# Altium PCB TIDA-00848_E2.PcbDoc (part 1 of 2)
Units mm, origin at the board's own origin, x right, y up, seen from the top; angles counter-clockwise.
Board outline 40 x 87.63 mm, 2 copper layers (Top Layer, Bottom Layer), stack 0.98 mm thick; 101 components, 66 nets, 314 pads, 292 vias.
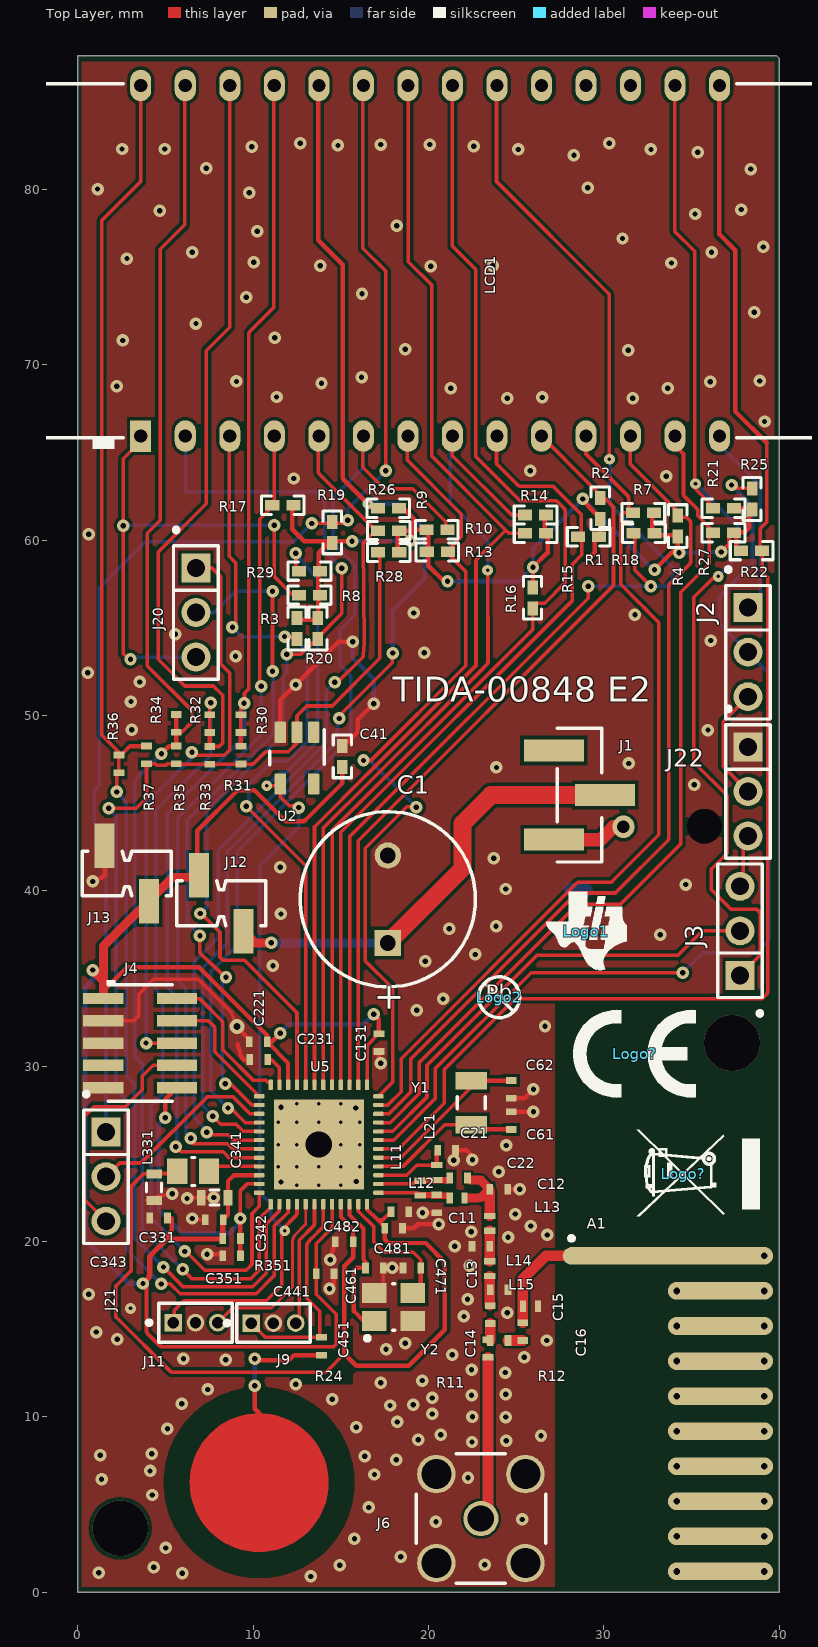
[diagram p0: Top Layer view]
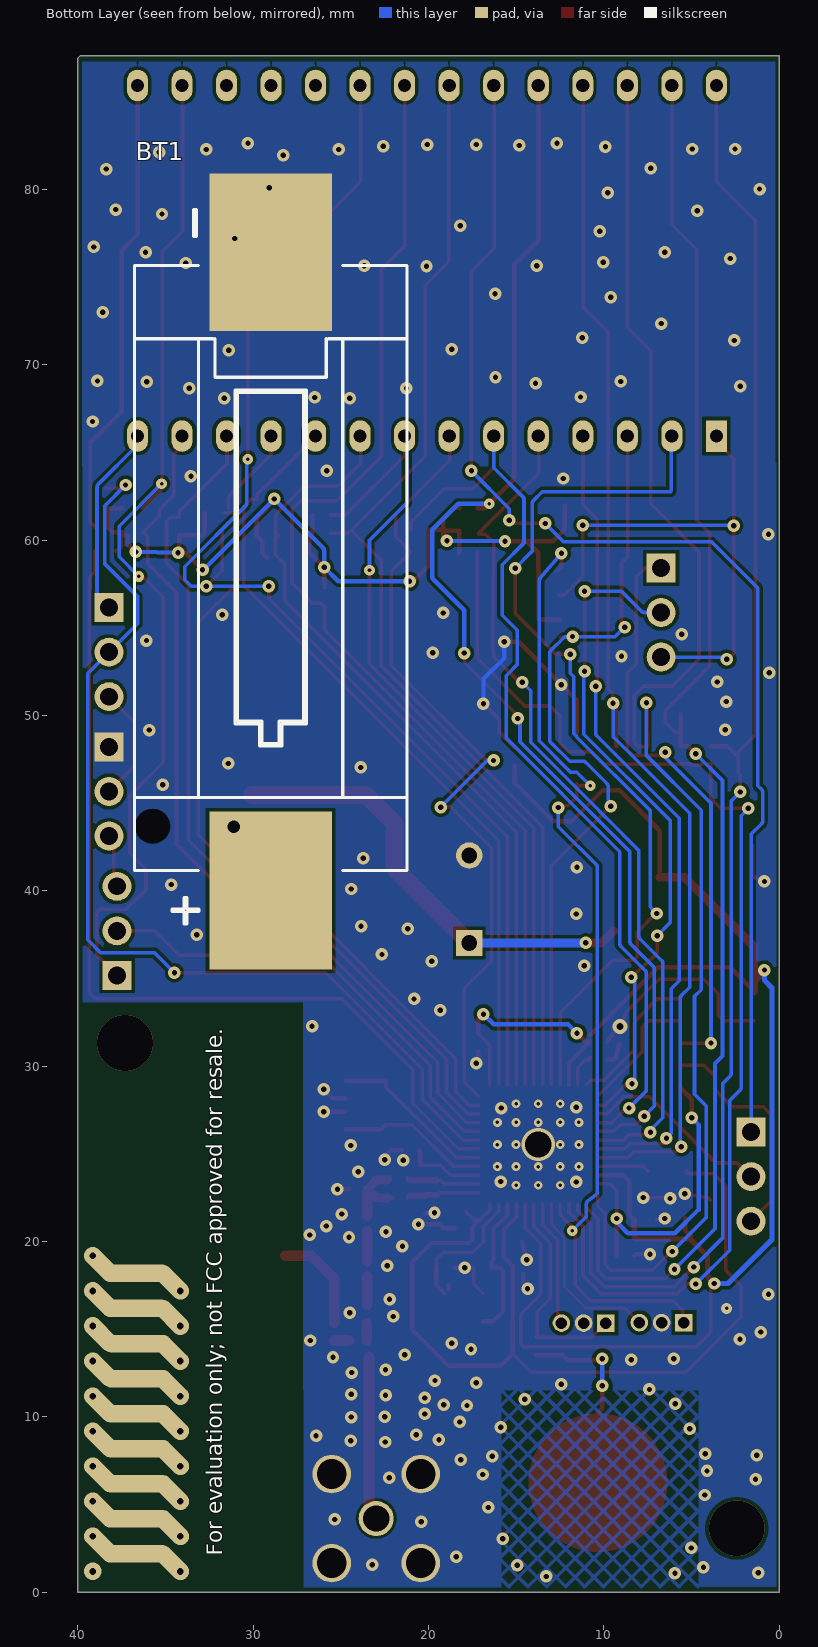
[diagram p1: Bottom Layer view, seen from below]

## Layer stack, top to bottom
Top Solder: solder mask 0.0102, Solder Resist, Dk 3.5
Top Layer: signal copper 0.035
Dielectric1: core 0.91, FR-4, Dk 4.6
Bottom Layer: signal copper 0.035
Bottom Solder: solder mask 0.0102, Solder Resist, Dk 3.5

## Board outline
0,0 40,0 40,87.508 39.878,87.63 0,87.63

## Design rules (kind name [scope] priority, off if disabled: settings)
AssemblyTestPointUsage [All] p1: valid=2
Clearance Clearance_Keepouts [((IsTrack Or IsArc) And Not InPoly) And IsFree and IsKeepOut vs ((IsTrack Or IsArc) And Not InPoly) And IsFree and IsKeepOut] p1: gap=0 ignorepadtopadclearanceinfootprint=FALSE
Clearance Clearance_BoardEdge_MountingHoles [OnCopper and InComponentClass('Mounting Holes') vs IsKeepOut] p2: gap=1.016 ignorepadtopadclearanceinfootprint=FALSE except(0: Arc-Hole Track-Hole SMDPad-Hole THPad-Hole Via-Hole Fill-Hole Poly-Hole Region-Hole Text-Hole)
Clearance Clearance_BoardEdge_Poly [OnCopper and InPoly vs IsKeepOut] p3: gap=0.635 ignorepadtopadclearanceinfootprint=FALSE except(0: Arc-Hole Track-Hole SMDPad-Hole THPad-Hole Via-Hole Fill-Hole Poly-Hole Region-Hole Text-Hole)
Clearance Clearance_BoardEdge [OnCopper and Not InComponentClass('Logo') and not InComponentClass('FiducialMark') and not InRegion(1000,500,4000,800) and Not IsKeepout vs IsKeepOut] p4: gap=1.905 ignorepadtopadclearanceinfootprint=FALSE except(0: Arc-Hole Track-Hole SMDPad-Hole THPad-Hole Via-Hole Fill-Hole Poly-Hole Region-Hole Text-Hole)
Clearance Clearance_CAP [InNet('CAP_EL') vs InNet('GND')] p5: gap=1.5 ignorepadtopadclearanceinfootprint=FALSE except(0: Arc-Hole Track-Hole SMDPad-Hole THPad-Hole Via-Hole Fill-Hole Poly-Hole Region-Hole Text-Hole; 0.254: Arc-Track Arc-SMDPad Arc-THPad Arc-Via Track-Track Track-Via Track-Poly SMDPad-Via THPad-Via Via-Via Via-Fill Via-Poly)
Clearance Clearance_015 [InPolygon vs (InNet('NetC12_1') OR InNet('NetC13_1') OR InNet('NetC14_1') OR InNet('NetC15_2') OR InNet('NetC16_2') OR InNet('NetA1_1') OR InNet('NetJ6_1') )] p6: gap=0.15 ignorepadtopadclearanceinfootprint=FALSE except(0: Arc-Hole Track-Hole SMDPad-Hole THPad-Hole Via-Hole Fill-Hole Poly-Hole Region-Hole Text-Hole)
Clearance Clearance_Poly [InPolygon] p7: gap=0.2 ignorepadtopadclearanceinfootprint=FALSE except(0: Arc-Hole Track-Hole SMDPad-Hole THPad-Hole Via-Hole Fill-Hole Poly-Hole Region-Hole Text-Hole)
Clearance [All] p8: gap=0.2 ignorepadtopadclearanceinfootprint=FALSE except(0: Arc-Hole Track-Hole SMDPad-Hole THPad-Hole Via-Hole Fill-Hole Poly-Hole Region-Hole Text-Hole)
ComponentClearance [All] p1: gap=0.254 collisioncheckmode=3 verticalgap=0.254 showdistances=TRUE
DiffPairsRouting [All] p1: maxlimit=2.54 minlimit=0.254 mostfreqgap=0.254 toplayer_minwidth=0.381 toplayer_maxwidth=0.381 toplayer_prefwidth=0.381 bottomlayer_minwidth=0.381 bottomlayer_maxwidth=0.381 bottomlayer_prefwidth=0.381 maxuncoupledlength=25.4
FabricationTestPointUsage TestPointUsage [All] p1: valid=2 allowmultiple=FALSE
FabricationTestpoint Testpoint [All] p1: side=3 testpointundercomponent=TRUE minsize=1.016 maxsize=2.54 preferedsize=1.524 minholesize=0 maxholesize=1.016 preferedholesize=0.813 testpointgrid=0.025 allowsidetop=TRUE allowsidebottom=TRUE usegrid=TRUE gridtolerance=0
FanoutControl Fanout_LCC [IsLCC] p1: bgadir=Out bgaviamode=Centered fanoutstyle=Auto fanoutdirection=Alternating viagrid=0.025 // Fanout_LCC (Default Rule)
FanoutControl Fanout_BGA [IsBGA] p2: bgadir=Out bgaviamode=Centered fanoutstyle=Auto fanoutdirection=Alternating viagrid=0.025 // Fanout_BGA (Default Rule)
FanoutControl Fanout_Default [All] p4: bgadir=Out bgaviamode=Centered fanoutstyle=Auto fanoutdirection=Alternating viagrid=0.025 // Fanout_Default (Default Rule)
FanoutControl Fanout_Small [(CompPinCount < 5)] p5: bgadir=Out bgaviamode=Centered fanoutstyle=Auto fanoutdirection=OutThenIn viagrid=0.025 // Fanout_Small (Default Rule)
HoleSize [All] p1: absolutevalues=TRUE maxlimit=6 minlimit=0.2 maxpercent=80.000 minpercent=20.000
HoleSize FabricationTestpoint [All] p2 off: absolutevalues=TRUE maxlimit=2.54 minlimit=0.025 maxpercent=80.000 minpercent=20.000
HoleSize FabricationTestPointUsage [All] p3 off: absolutevalues=TRUE maxlimit=2.54 minlimit=0.025 maxpercent=80.000 minpercent=20.000
MinimumSolderMaskSliver [All] p1: minsoldermaskwidth=0.152
PlaneClearance [All] p1: clearance=0.2
PlaneConnect [All] p1: planeconnectstyle=Relief reliefexpansion=0.254 reliefentries=4 reliefconductorwidth=0.254 reliefairgap=0.254
PolygonConnect PolygonConnect_GND [HasPad('U5-49') OR HasPad('U4')] p1: connectstyle=NoConnect reliefconductorwidth=0.254 reliefentries=4 polygonreliefangle="90 Angle" airgapwidth=0.254
PolygonConnect [All] p2: connectstyle=Direct reliefconductorwidth=0.254 reliefentries=4 polygonreliefangle="90 Angle" airgapwidth=0.254
RoutingVias ThermalPadVias [IsVia and InAnyComponent] p1: holewidth=0.2 width=0.5 viastyle="Through Hole" minholewidth=0.2 minwidth=0.5 maxholewidth=0.39 maxwidth=0.6
RoutingVias [All] p2: holewidth=0.2 width=0.864 viastyle="Through Hole" minholewidth=0.2 minwidth=0.66 maxholewidth=0.4 maxwidth=1.651
SilkToSilkClearance [All] p1: silktosilkclearance=0.178
SilkToSolderMaskClearance [IsPad] p1: minsilkscreentomaskgap=0.152 clearancetoexposedcopper=TRUE
SolderMaskExpansion [All] p1: expansion=0.05 istentingtop=FALSE
SupplyNets "Schematic Supply Nets_5" [InNet('VCC_430')] p1: voltage=0.000
SupplyNets "Schematic Supply Nets_4" [InNet('VCC_IN')] p2: voltage=0.000
SupplyNets "Schematic Supply Nets_3" [InNet('VDDS')] p3: voltage=0.000
SupplyNets "Schematic Supply Nets_2" [InNet('VCC_EXTERN')] p4: voltage=0.000
SupplyNets "Schematic Supply Nets_1" [InNet('GND')] p5: voltage=0.000
SupplyNets "Schematic Supply Nets" [InNet('VDDR')] p6: voltage=0.000
Width [All] p1: maxlimit=2.54 minlimit=0.152 preferedwidth=0.254 checkconnectedcopper=TRUE
15 further rules are at their usual default settings.

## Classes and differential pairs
component class Header: J1 J2 J3 J4 J9 J11 J12 J13 J20 J21 J22
component class TIDA-00848_RF_E2: A1 C11 C12 C13 C14 C15 C16 C21 C22 C61 C62 C131 C221 C231 C331 C341 C342 C343 C351 C441 C451 C461 C471 C481 C482 J4 J6 J9 J11 L11 L12 L13 L14 L15 L21 L331 R11 R12 R24 R351 U5 Y1 Y2
component class TIDA-00848_LCD_E2: BT1 C1 C41 J1 J2 J3 J12 J13 J20 J21 J22 LCD1 R1 R2 R3 R4 R7 R8 R9 R10 R13 R14 R15 R16 R17 R18 R19 R20 R21 R22 R25 R26 R27 R28 R29 R30 R31 R32 R33 R34 R35 R36 R37 U2
component class Logo: Logo1
component class TIDA-00848__Hardware_E2: FID1 FID2 H9 H10 H11 Logo1 Logo2 Logo? ZZ2 ZZ3 ZZ4
component class FiducialMark: FID1 FID2
component class AssemblyNote: ZZ2 ZZ3 ZZ4

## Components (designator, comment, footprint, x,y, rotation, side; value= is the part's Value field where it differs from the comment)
A1 "ANTENNA_HELICAL" ANTENNA_HELICAL 28.155,19.177 r270 top locked net-tie
BT1 "1010" BAT_1010 29.008,58.228 r90 bottom locked
C1 "EEUFM1A122" CAPPR5-10X20 17.678,39.522 r90 top locked value=1200uF
C11 "Comment" 0402S 20.472,22.149 r90 top value=3.6pF
C12 "GRM1555C1H2R7CA01D" 0402S 24.003,22.987 r0 top value=2.7pF
C13 "GRM1555C1H6R2CA01D" 0402S 22.987,19.736 r180 top value=6.2pF
C14 "GRM1555C1H3R3CA01D" 0402S 24.028,17.247 r0 top value=3.3pF
C15 "GRM1555C1H101JA01D" 0402S 23.52,15.824 r270 top value=100pF
C16 "GRM1555C1H1R0CA01D" 0402S 25.375,14.859 r270 top value=1pF
C21 "GRM1555C1H101JA01D" 0402S 21.029,25.203 r180 top value=100pF
C22 "GRM1555C1H3R6CA01D" 0402S 21.717,23.622 r0 top value=3.6pF
C41 "CMP-0006607-2" 0402 15.088,47.676 r90 top value=0.1uF
C61 "Comment" 0402S 24.714,26.899 r90 top value=12pF
C62 "GRM1555C1H120JA01D" 0402S 24.714,28.677 r270 top value=12pF
C131 "Comment" 0402S 17.17,31.344 r270 top value=0.1uF
C221 "Comment" 0402S 10.287,31.394 r180 top value=0.1uF
C231 "Comment" 0402S 10.312,30.378 r180 top value=1uF
C331 "GRM188R60J226MEA0J" 0603S 4.343,23.089 r270 top value=22uF
C341 "GRM188R60J226MEA0J" 0603S 7.798,22.504 r180 top value=22uF
C342 "GRM155R61E104KA87D" 0402S 7.772,21.234 r180 top value=0.1uF
C343 "GRM155R61E104KA87D" 0402S 4.597,21.336 r180 top value=0.1uF
C351 "GRM155R70J104KA01D" 0402S 8.763,19.177 r180 top value=0.1uF
C441 "GRM155R70J104KA01D" 0402S 14.097,18.161 r0 top value=0.1uF
C451 "GRM155R70J104KA01D" 0402S 15.189,19.99 r180 top value=0.1uF
C461 "DNM" 0402S 16.916,18.491 r0 top value=12pF
C471 "DNM" 0402S 19.05,18.491 r180 top value=12pF
C481 "GRM155R70J104KA01D" 0402S 18.009,20.752 r0 top value=0.1uF
C482 "GRM155R70J104KA01D" 0402S 18.364,21.692 r0 top value=0.1uF
FID1 "Fiducial" Fiducial10-20 53.721,1.092 r0 top
FID2 "Fiducial" Fiducial10-20 57.963,1.092 r0 top
FID3 "Fiducial" Fiducial10-20 62.23,1.092 r0 top
H9 "SJ-5303 (CLEAR)" Bumpon_SJ5003Transparent 82.474,13.259 r0 top
H10 "SJ-5303 (CLEAR)" Bumpon_SJ5003Transparent 55.728,13.03 r0 top
H11 "SJ-5303 (CLEAR)" Bumpon_SJ5003Transparent 69.215,13.183 r0 top
J1 "TSM-103-01-L-SV" Samtec_TSM-103-01-X-SV 28.613,45.466 r90 top
J2 "TSW-103-07-G-S" TSW-103-07-G-S 38.227,53.619 r270 top
J3 "TSW-103-07-G-S" TSW-103-07-G-S 37.77,37.719 r90 top
J4 "CMP-0075159-2" Gradconn_BB02-BS101-xAx-025B00 3.548,31.318 r0 top locked
J6 "901-144-8RFX" Amphenol_901-144-8RFX 22.987,4.191 r0 top locked
J9 "850-10-003-10-001000" Mill-Max_850-10-003-10-001000 11.151,15.342 r0 top
J11 "850-10-003-10-001000" Mill-Max_850-10-003-10-001000 6.706,15.367 r0 top
J12 "HW-02-15-T-S-340-SM" Samtec_HW-02-15-X-S-340-SM 8.179,39.294 r180 top locked
J13 "HW-02-15-T-S-340-SM" Samtec_HW-02-15-X-S-340-SM 2.794,40.996 r180 top locked
J20 "TSW-103-07-G-S" TSW-103-07-G-S 6.731,55.88 r270 top
J21 "TSW-103-07-G-S" TSW-103-07-G-S 1.6,23.698 r270 top
J22 "TSW-103-07-G-S" TSW-103-07-G-S 38.227,45.669 r270 top
L11 "LQW15AN18NJ00D" LQW15A_00_10 19.533,23.038 r270 top value=18nH
L12 "LQW15AN7N5G00D" LQW15A_00_10 21.634,22.479 r0 top value=7.5nH
L13 "LQW15AN6N8G00D" LQW15A_00_10 23.495,21.038 r270 top value=6.8nH
L14 "LQW15AN6N8G00D" LQW15A_00_10 23.495,18.447 r270 top value=6.8nH
L15 "LQW15AN12NJ00D" LQW15A_00_10 25.813,16.307 r180 top value=12nH
L21 "LQW15AN7N5G00D" LQW15A_00_10 20.472,23.927 r270 top value=7.5nH
L331 "MLZ2012N6R8LT000" 0805_145 6.568,24.003 r180 top value=6.8uH
LCD1 "BTL002" TI_BTL002 20.091,75.946 r90 top
Logo1 "Texas Instruments" TI_Symbol_Overlay_Small 29.008,37.705 r0 top
Logo2 "Pb-Free Symbol" Pb-Free_Overlay_Small 24.028,33.934 r0 top
Logo? "WEEE logo" WEEE_Minimum 34.519,23.851 r90 top
Logo? "FCC disclaimer" FCC_disclaimer -18.847,49.479 r90 top
Logo? "CE Mark" CE_Mark_5mm 31.75,30.709 r0 top
R1 "CMP-0026826-2" 0402 29.134,60.198 r0 top value=10Meg
R2 "CMP-0026826-2" 0402 29.794,61.824 r270 top value=10Meg
R3 "CMP-0026826-2" 0402 12.497,54.966 r90 top value=10Meg
R4 "CMP-0026826-2" 0402 34.214,60.808 r270 top value=10Meg
R7 "CMP-0026826-2" 0402 32.258,61.57 r0 top value=10Meg
R8 "CMP-0026826-2" 0402 13.208,56.871 r0 top value=10Meg
R9 "CMP-0026826-2" 0402 17.729,60.554 r0 top value=10Meg
R10 "CMP-0026826-2" 0402 20.472,60.604 r180 top value=10Meg
R11 "CRCW04020000Z0ED" 0402S 23.393,13.894 r270 top value=0
R12 "Comment" 0402S 24.028,14.351 r0 top value=0
R13 "CMP-0026826-2" 0402 20.498,59.334 r180 top value=10Meg
R14 "CMP-0026826-2" 0402 26.111,61.443 r0 top value=10Meg
R15 "CMP-0026826-2" 0402 26.111,60.401 r180 top value=10Meg
R16 "CMP-0026826-2" 0402 25.933,56.718 r270 top value=10Meg
R17 "CMP-0026826-2" 0402 11.684,62.001 r180 top value=10Meg
R18 "CMP-0026826-2" 0402 32.283,60.401 r180 top value=10Meg
R19 "CMP-0026826-2" 0402 14.503,60.452 r90 top value=10Meg
R20 "CMP-0026826-2" 0402 13.691,54.966 r270 top value=10Meg
R21 "CMP-0026826-2" 0402 36.83,61.824 r180 top value=10Meg
R22 "CMP-0026826-2" 0402 38.43,59.411 r0 top value=10Meg
R24 "CRCW04020000Z0ED" 0402S 13.894,14.021 r90 top value=0
R25 "CMP-0026826-2" 0402 38.456,62.357 r90 top value=10Meg
R26 "CMP-0026826-2" 0402 17.704,61.824 r180 top value=10Meg
R27 "CMP-0026826-2" 0402 36.83,60.427 r180 top value=10Meg
R28 "CRCW04021M00FKED" 0402 17.729,59.309 r0 top value=1.00Meg
R29 "CRCW04022M00FKED" 0402 13.208,58.242 r180 top value=2.00Meg
R30 "CRCW04021M00FKED" 0402S 9.296,49.546 r90 top value=1.00Meg
R31 "CRCW04022M00FKED" 0402S 9.296,47.743 r270 top value=2.00Meg
R32 "CRCW04021M00FKED" 0402S 7.518,49.546 r90 top value=1.00Meg
R33 "CRCW04022M00FKED" 0402S 7.518,47.727 r270 top value=2.00Meg
R34 "CRCW04021M00FKED" 0402S 5.613,49.555 r90 top value=1.00Meg
R35 "CRCW04022M00FKED" 0402S 5.613,47.752 r270 top value=2.00Meg
R36 "CRCW04021M00FKED" 0402S 2.337,47.244 r270 top value=1.00Meg
R37 "CRCW04022M00FKED" 0402S 3.912,47.752 r270 top value=2.00Meg
R351 "ERJ-2RKF1003X" 0402S 8.763,20.168 r180 top value=100k
U2 "SN74AHC1G04DBV" DBV0005A_M 12.497,47.574 r270 top
U5 "CMP-0076688-3" RGZ0048A 13.745,25.531 r180 top locked
Y1 "FC-135 32.7680KA-A3" Epson_FC-135 22.428,27.915 r90 top
Y2 "CMP-0004609-3" EPSON_TSX-3225 18.009,16.256 r90 top
ZZ2 "These assemblies are ESD sensitive, ESD precautions shall be observed." AssemblyNote -91.821,111.737 r0 top
ZZ3 "These assemblies must be clean and free from flux and all contaminants. Use of no clean flux is not acceptable." AssemblyNote -91.821,109.488 r0 top
ZZ4 "These assemblies must comply with workmanship standards IPC-A-610 Class 2, unless otherwise specified." AssemblyNote -91.821,107.239 r0 top

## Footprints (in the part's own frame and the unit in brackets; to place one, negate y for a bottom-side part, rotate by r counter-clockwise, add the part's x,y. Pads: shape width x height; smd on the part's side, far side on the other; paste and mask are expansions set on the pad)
0402 [mm] "0402 from SM-752 data"
  rect 0.8x0.6 smd: 1(-0.6,0) 2(0.6,0)
  silkscreen extent -1.22,-0.52 1.22,0.52, body extent -0.55,-0.3 0.55,0.3, height 0.6
0402S [mil] "Based on C0402S footprint from PADS legacy"
  rect 15x24 smd: 1(-20,0) 2(20,0)
  body extent -22,-12 22,12, height 24
0603S [mil]
  rect 20x35 smd: 1(-30,0) 2(30,0)
  silkscreen extent -10,-17 10,17, body extent -34,-19 34,19, height 33
0805_145 [mm] "0805 / 1.45mm height"
  rect 1.15x1.45 smd: 1(-0.9,0) 2(0.9,0)
  silkscreen extent -0.1,-0.8 0.1,0.8, body extent -1.1,-0.72 1.1,0.72, height 1.45
Amphenol_901-144-8RFX [mm] "SMA Straight Jack, TH"
  round 2 hole 1.5: 1(0,0)
  round 2.2 hole 1.7: 2(-2.54,2.54) 3(-2.54,-2.54) 4(2.54,-2.54) 5(2.54,2.54)
  silkscreen extent -3.7,-3.7 3.7,3.7, body extent -3.7,-3.7 3.7,3.7, height 9.93
ANTENNA_HELICAL [mm] "SMD, 1-Lead"
  round 1 smd paste-1 mask-1: 1(0,0)
  oval 1x12 smd paste-12 mask-12: ""(0,5.5)
  oval 1x2.414 smd far side rot 45 paste-1.5 mask-1.5: ""(0.5,10.5) ""(1.5,6.5) ""(2.5,10.5) ""(3.5,6.5) ""(4.5,10.5) ""(5.5,6.5) ""(6.5,10.5) ""(7.5,6.5) ""(8.5,10.5) ""(9.5,6.5) ""(10.5,10.5) ""(11.5,6.5) ""(12.5,10.5) ""(13.5,6.5) ""(14.5,10.5) ""(15.5,6.5) ""(16.5,10.5) ""(17.5,6.5)
  oval 1x4 smd far side paste-4 mask-4: ""(1,8.5) ""(3,8.5) ""(5,8.5) ""(7,8.5) ""(9,8.5) ""(11,8.5) ""(13,8.5) ""(15,8.5) ""(17,8.5)
  oval 1x6 smd paste-6 mask-6: ""(2,8.5) ""(4,8.5) ""(6,8.5) ""(8,8.5) ""(10,8.5) ""(12,8.5) ""(14,8.5) ""(16,8.5) ""(18,8.5)
  silkscreen extent -1.12,-0.12 -0.88,0.13
AssemblyNote [mm] "Assembly Note"
BAT_1010 [mm] "Keystone"
  round 0.94 hole 1.994 unplated: 0(-14.54,6.73)
  rect 9x7 smd: 1(-18.21,0) 2(18.21,0)
  silkscreen extent -20.12,-7.77 20.64,7.77, body extent -21.7,-7.77 22.07,7.77, height 15.06
Bumpon_SJ5003Transparent [mil] "3M Hemispherical Bumpon transparent"
  round 1 on Mech3: 0(0,0)
  silkscreen extent -228,-228 228,228, body extent -217,-218 219,218, height 197
CAPPR5-10X20 [mm] "Capacitor, Electrolytic, Radial; Body 10 x 20 mm (Dia.xH typ); Pin Spacing 5 mm (typ)"
  rect 1.5x1.5 hole 0.9: 1(-2.5,0)
  round 1.5 hole 0.9: 2(2.5,0)
  silkscreen extent -5,-5 5,5, body extent -5,-5 5,5, height 22
CE_Mark_5mm [mm] "Minimum text height for CE Mark"
  silkscreen extent -3.5,-2.5 3.5,2.5
DBV0005A_M [mm] "SOT23, 5-Leads, Body 2.9x1.6mm, Pitch 0.95mm, Lead Span 2.8mm, IPC Low Density"
  rrect15% 1.2x0.65 smd: 1(-1.475,0.95) 2(-1.475,0) 3(-1.475,-0.95) 4(1.475,-0.95) 5(1.475,0.95)
  silkscreen extent -1.63,-1.55 0.38,1.55, body extent -1.42,-1.46 1.42,1.46, height 1.09
Epson_FC-135 [mm] "SMD, 2-Leads, Body 3.2x1.5mm"
  rect 1x1.8 smd: 1(-1.25,0) 2(1.25,0)
  silkscreen extent -0.35,-0.8 0.35,0.8, body extent -1.65,-0.8 1.65,0.8, height 0.9
EPSON_TSX-3225 [mm] "SMD, 4-Leads, Body 2.65x3.35mm, Height 0.6mm"
  rect 1.15x1.4 smd: 1(-0.8,1.1) 2(-0.8,-1.1) 3(0.8,-1.1) 4(0.8,1.1)
  silkscreen extent -1.9,-0.05 1.33,1.62, body extent -1.33,-1.68 1.33,1.68, height 0.61
FCC_disclaimer [mm]
Fiducial10-20 [mm]
  round 1 smd mask+0.5: 1(0,0)
  Top Layer keep-out circle w1.178: c0,0 r0.5
Gradconn_BB02-BS101-xAx-025B00 [mm] "Header, 1.27mm, 5x2, SMT"
  rect 2.3x0.65 smd: 1(-2.1,2.54) 2(2.1,2.54) 3(-2.1,1.27) 4(2.1,1.27) 5(-2.1,0) 6(2.1,0) 7(-2.1,-1.27) 8(2.1,-1.27) 9(-2.1,-2.54) 10(2.1,-2.54)
  silkscreen extent -1.92,-3.32 1.83,3.6, body extent -2.75,-3.32 2.75,3.32, height 4.25
LQW15A_00_10 [mm] "Murata"
  rect 0.35x0.65 smd: 1(-0.425,0) 2(0.425,0)
  body extent -0.55,-0.35 0.55,0.35, height 0.6
Mill-Max_850-10-003-10-001000 [mm] "Header, 1.27 mm, 3x1, Gold, Straight, TH"
  rect 1x1 hole 0.65: 1(-1.27,0)
  round 1 hole 0.65: 2(0,0) 3(1.27,0)
  silkscreen extent -2.77,-1.1 2.09,1.1, body extent -2.1,-1.1 2.1,1.1, height 5.21
Pb-Free_Overlay_Small [mm]
  silkscreen extent -1.16,-1.17 1.17,1.17
RGZ0048A [mm] "VQFN-48"
  rrect42% 0.6x0.24 smd: 1(-3.4,2.75) 2(-3.4,2.25) 3(-3.4,1.75) 4(-3.4,1.25) 5(-3.4,0.75) 6(-3.4,0.25) 7(-3.4,-0.25) 8(-3.4,-0.75) 9(-3.4,-1.25) 10(-3.4,-1.75) 11(-3.4,-2.25) 12(-3.4,-2.75) 25(3.4,-2.75) 26(3.4,-2.25) 27(3.4,-1.75) 28(3.4,-1.25) 29(3.4,-0.75) 30(3.4,-0.25) 31(3.4,0.25) 32(3.4,0.75) 33(3.4,1.25) 34(3.4,1.75) 35(3.4,2.25) 36(3.4,2.75)
  rrect42% 0.24x0.6 smd: 13(-2.75,-3.4) 14(-2.25,-3.4) 15(-1.75,-3.4) 16(-1.25,-3.4) 17(-0.75,-3.4) 18(-0.25,-3.4) 19(0.25,-3.4) 20(0.75,-3.4) 21(1.25,-3.4) 22(1.75,-3.4) 23(2.25,-3.4) 24(2.75,-3.4) 37(2.75,3.4) 38(2.25,3.4) 39(1.75,3.4) 40(1.25,3.4) 41(0.75,3.4) 42(0.25,3.4) 43(-0.25,3.4) 44(-0.75,3.4) 45(-1.25,3.4) 46(-1.75,3.4) 47(-2.25,3.4) 48(-2.75,3.4)
  rrect2% 5.15x5.15 smd paste-2.6: 49(0,0)
  body extent -3.5,-3.5 3.5,3.5, height 1
Samtec_HW-02-15-X-S-340-SM [mil] "SMD, 2-Leads, Body 100x200mil, Pitch 100mil"
  rect 45x100 smd: 1(-50,62.5) 2(50,-62.5)
  silkscreen extent -100,-50 100,50, body extent -100,-92 100,92, height 565
Samtec_TSM-103-01-X-SV [mil] "Samtec recommended land pattern"
  rect 50x135 smd: 1(-100,57.5) 2(0,-57.5) 3(100,57.5)
  silkscreen extent -150,-50 150,50, body extent -150,-104 150,104, height 381
TI_BTL002 [mm] "TH, 28-Leads, Body 44x20mm, Pitch 2.54mm"
  rect 1.8x1.2 hole 0.75: 1(-10,16.51)
  oval 1.8x1.2 hole 0.75: 2(-10,13.97) 3(-10,11.43) 4(-10,8.89) 5(-10,6.35) 6(-10,3.81) 7(-10,1.27) 8(-10,-1.27) 9(-10,-3.81) 10(-10,-6.35) 11(-10,-8.89) 12(-10,-11.43) 13(-10,-13.97) 14(-10,-16.51) 15(10,-16.51) 16(10,-13.97) 17(10,-11.43) 18(10,-8.89) 19(10,-6.35) 20(10,-3.81) 21(10,-1.27) 22(10,1.27) 23(10,3.81) 24(10,6.35) 25(10,8.89) 26(10,11.43) 27(10,13.97) 28(10,16.51)
  silkscreen extent -10.75,-22.1 10.1,22.1, body extent -10.1,-22.1 10.1,22.1, height 2
TI_Symbol_Overlay_Small [mm]
  silkscreen extent -2.3,-2.23 2.3,2.24
TSW-103-07-G-S [mm]
  rect 1.65x1.65 hole 1.016 mask+0: 1(-2.54,0)
  round 1.65 hole 1.016 mask+0: 2(0,0) 3(2.54,0)
  silkscreen extent -4.83,-1.27 3.81,1.27, body extent -3.81,-1.27 3.81,1.27, height 8.38
WEEE_Minimum [mm] "WEEElie bin"
  silkscreen extent -2.42,-4.38 2.52,2.65

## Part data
A1: "PCB Antenna. There is nothing to buy or mount.", Manufacturer=N/A
BT1: "Battery Holder, Nylon, CR2, SMT", Manufacturer=Keystone, Supplier Part Number 1=1010K-ND
C1: "CAP, AL, 1200 µF, 10 V, +/- 20%, TH", Cap_Case=10x20, Manufacturer=Panasonic, Supplier Part Number 1=P12355-ND, Tolerance_%=20, Value1=Unknown, Value2=10V, ValueDisplayed=1200µF
C11: library part GRM1555C1H3R6CA01D, "CAP, CERM, 3.6 pF, 50 V, +/- 5%, C0G/NP0, 0402", Cap_Case=0402, Manufacturer=MuRata, Supplier Part Number 1=81-GRM1555C1H3R6CA1D, TempCo=C0G/NP0, Tolerance_%=5, Value1=Unknown, Value2=50V, ValueDisplayed=3.6pF
C12: "CAP, CERM, 2.7 pF, 50 V, +/- 5%, C0G/NP0, 0402", Cap_Case=0402, Manufacturer=MuRata, Supplier Part Number 1=81-GRM1555C1H2R7CA1D, TempCo=C0G/NP0, Tolerance_%=5, Value1=Unknown, Value2=50V, ValueDisplayed=2.7pF
C13: "CAP, CERM, 6.2 pF, 50 V, +/- 5%, C0G/NP0, 0402", Cap_Case=0402, Manufacturer=MuRata, Supplier Part Number 1=81-GRM1555C1H6R2CA1D, TempCo=C0G/NP0, Tolerance_%=5, Value1=Unknown, Value2=50V, ValueDisplayed=6.2pF
C14: "CAP, CERM, 3.3 pF, 50 V, +/- 5%, C0G/NP0, 0402", Cap_Case=0402, Manufacturer=MuRata, Supplier Part Number 1=81-GRM1555C1H3R3CA1D, TempCo=C0G/NP0, Tolerance_%=5, Value1=Unknown, Value2=50V, ValueDisplayed=3.3pF
C15 C21: "CAP, CERM, 100 pF, 50 V, +/- 5%, C0G/NP0, 0402", Cap_Case=0402, Manufacturer=MuRata, Supplier Part Number 1=81-GRM1555C1H101JA1D, TempCo=C0G/NP0, Tolerance_%=5, Value1=Unknown, Value2=50V, ValueDisplayed=100pF
C16: "CAP, CERM, 1 pF, 50 V, +/- 5%, C0G/NP0, 0402", Cap_Case=0402, Manufacturer=MuRata, Supplier Part Number 1=490-3199-1-ND, TempCo=C0G/NP0, Tolerance_%=5, Value1=Unknown, Value2=50V, ValueDisplayed=1pF
C22: "CAP, CERM, 3.6 pF, 50 V, +/- 5%, C0G/NP0, 0402", Cap_Case=0402, Manufacturer=MuRata, Supplier Part Number 1=81-GRM1555C1H3R6CA1D, TempCo=C0G/NP0, Tolerance_%=5, Value1=Unknown, Value2=50V, ValueDisplayed=3.6pF
C41: "CAP, CERM, 0.1 uF, 25 V, +/- 10%, X5R, 0402", Cap_Case=0402, Manufacturer=MuRata, PartNumber=GRM155R61E104KA87D, Supplier Part Number 1=490-5920-1-ND, TempCo=X5R, Tolerance_%=10%, Value1=Unknown, Value2=25V, ValueDisplayed=0.1uF
C61: library part GRM1555C1H120JA01D, "CAP, CERM, 12 pF, 50 V, +/- 5%, C0G/NP0, 0402", Cap_Case=0402, Manufacturer=MuRata, Supplier Part Number 1=81-GRM1555C1H120JA1D, TempCo=C0G/NP0, Tolerance_%=5, Value1=Unknown, Value2=50V, ValueDisplayed=12pF
C62: "CAP, CERM, 12 pF, 50 V, +/- 5%, C0G/NP0, 0402", Cap_Case=0402, Manufacturer=MuRata, Supplier Part Number 1=81-GRM1555C1H120JA1D, TempCo=C0G/NP0, Tolerance_%=5, Value1=Unknown, Value2=50V, ValueDisplayed=12pF
C131 C221: library part GRM155R70J104KA01D, "CAP, CERM, 0.1 µF, 6.3 V, +/- 10%, X7R, 0402", Cap_Case=0402, Manufacturer=MuRata, Supplier Part Number 1=GRM155R70J104KA01D-ND, TempCo=X7R, Tolerance_%=10, Value1=Unknown, Value2=6.3V, ValueDisplayed=0.1µF
C231: library part GRM155R61A105KE15D, "CAP, CERM, 1 µF, 10 V, +/- 10%, X5R, 0402", Cap_Case=0402, Manufacturer=MuRata, Supplier Part Number 1=490-3890-1-ND, TempCo=X5R, Tolerance_%=10, Value1=Unknown, Value2=10V, ValueDisplayed=1µF
C331 C341: "CAP, CERM, 22 µF, 6.3 V, +/- 20%, X5R, 0603", Cap_Case=0603, Manufacturer=MuRata, Supplier Part Number 1=490-7612-2-ND, TempCo=X5R, Tolerance_%=20, Value1=Unknown, Value2=6.3V, ValueDisplayed=22µF
C342 C343: "CAP, CERM, 0.1 µF, 25 V, +/- 10%, X5R, 0402", Cap_Case=0402, Manufacturer=MuRata, Supplier Part Number 1=81-GRM155R61E104KA7D, TempCo=X5R, Tolerance_%=10, Value1=Unknown, Value2=25V, ValueDisplayed=0.1µF
C351 C441 C451 C481: "CAP, CERM, 0.1 µF, 6.3 V, +/- 10%, X7R, 0402", Cap_Case=0402, Manufacturer=MuRata, Supplier Part Number 1=GRM155R70J104KA01D-ND, TempCo=X7R, Tolerance_%=10, Value1=Unknown, Value2=6.3V, ValueDisplayed=0.1µF
C461 C471: library part GRM1555C1H120JA01D, "CAP, CERM, 12 pF, 50 V, +/- 5%, C0G/NP0, 0402", Cap_Case=0402, Manufacturer=MuRata, Supplier Part Number 1=81-GRM1555C1H120JA1D, TempCo=C0G/NP0, Tolerance_%=5, Value1=Unknown, Value2=50V
C482: "CAP, CERM, 0.1 µF, 6.3 V, +/- 10%, X7R, 0402", Cap_Case=0402, Manufacturer=MuRata, Supplier Part Number 1=GRM155R70J104KA01D-ND, TempCo=X7R, Tolerance_%=10, Value1=Unknown, Value2=6.3V, ValueDisplayed=DNM
FID1 FID2 FID3: library part CMP-0077181-1, "Fiducial mark.  There is nothing to buy or mount.", Manufacturer=N/A
H9 H10 H11: "Bumpon, Hemisphere, 0.44 X 0.20, Clear", Manufacturer=3M, Supplier Part Number 1=SJ5303-7-ND
J1: "Header, 100mil, 3x1, Gold, SMT", Manufacturer=Samtec, Supplier Part Number 1=TSM-103-01-L-SV-ND
J2 J3 J20 J21 J22: "Header, TH, 100mil, 3x1, Gold plated, 230 mil above insulator", Manufacturer=Samtec, Supplier Part Number 1=SAM1029-03-ND
J4: "Header, 1.27mm, 5x2, SMT", Manufacturer=GradConn, PartNumber=BB02-BS101-KA8-025B00
J6: "SMA Straight Jack, Gold, 50 Ohm, TH", Manufacturer="Amphenol RF", Supplier Part Number 1=ARFX1231-ND
J9 J11: "Header, 50mil, 3x1, Gold, TH", Manufacturer=Mill-Max, Supplier Part Number 1=575-85013
J12 J13: "Header, 100mil, 2x1, Gold, SMD", Manufacturer=Samtec
L11: "Inductor, Wirewound, 18 nH, 0.37 A, 0.27 ohm, SMD", Manufacturer=MuRata, Supplier Part Number 1=490-1149-1-ND, Value1="0.27 ohm", Value2=0.37A, ValueDisplayed=18nH
L12 L21: "Inductor, Wirewound, 7.5 nH, 0.57 A, 0.13 ohm, SMD", Manufacturer=MuRata, Supplier Part Number 1=490-6846-1-ND, Value1="0.13 ohm", Value2=0.57A, ValueDisplayed=7.5nH
L13 L14: "Inductor, Wirewound, 6.8 nH, 0.7 A, 0.09 ohm, SMD", Manufacturer=MuRata, Supplier Part Number 1=490-6840-1-ND, Value1="0.09 ohm", Value2=0.7A, ValueDisplayed=6.8nH
L15: "Inductor, Wirewound, 12 nH, 0.5 A, 0.14 ohm, SMD", Manufacturer=MuRata, Supplier Part Number 1=490-1147-1-ND, Value1="0.14 ohm", Value2=0.5A, ValueDisplayed=12nH
L331: "Inductor, Multilayer, Ferrite, 6.8 µH, 0.11 A, 0.25 ohm, SMD", Manufacturer=TDK, Supplier Part Number 1=445-6761-1-ND, Value1="0.25 ohm", Value2=0.11A, ValueDisplayed=6.8µH
LCD1: library part CMP-0004933-1, "LCD, 96 segments, 4-MUX, TH", Manufacturer="Texas Instruments"
Logo1: library part TI_Logo, "Texas Instrument Corporate Signature"
Logo2: library part Pb-Free
Logo?: library part CMP-0074769-1
Logo?: library part CMP-0074847-1, "FCC_disclaimer"
Logo?: library part CMP-0074844-1
R1 R2 R3 R4 R7 R8 R9 R10 R13 R14 R15 R16 R17 R18 R19 R20 R21 R22 R25 R26 R27: "RES, 10 M, 5%, 0.063 W, AEC-Q200 Grade 0, 0402", Manufacturer=Vishay-Dale, PartNumber=CRCW040210M0JNED, Power_W=63mW, Supplier Part Number 1=541-10MJCT-ND, TempCo="200 ppm/C", Tolerance_%=5%, Value2=0.063W, Value_Code=10M0, ValueDisplayed=10M
R11 R24: "RES, 0, 5%, 0.063 W, 0402", Manufacturer=Vishay-Dale, Power_W=0.063, Supplier Part Number 1=541-0.0JCT-ND, TempCo="200 ppm/C", Tolerance_%=5, Value1=5%, Value2=0.063W, Value_Code=0000, ValueDisplayed=0
R12: library part CRCW04020000Z0ED, "RES, 0, 5%, 0.063 W, 0402", Manufacturer=Vishay-Dale, Power_W=0.063, Supplier Part Number 1=541-0.0JCT-ND, TempCo="200 ppm/C", Tolerance_%=5, Value1=5%, Value2=0.063W, Value_Code=0000, ValueDisplayed=DNM
R28 R30 R32 R34 R36: library part CMP-0026100-2, "RES, 1.00 M, 1%, 0.063 W, AEC-Q200 Grade 0, 0402", Manufacturer=Vishay-Dale, Power_W=63mW, Supplier Part Number 1=541-1.00MLCT-ND, TempCo="100 ppm/C", Tolerance_%=1%, Value2=0.063W, Value_Code=1M00, ValueDisplayed=1.00M
R29 R31 R33 R35 R37: library part CMP-0026245-2, "RES, 2.00 M, 1%, 0.063 W, AEC-Q200 Grade 0, 0402", Manufacturer=Vishay-Dale, Power_W=63mW, Supplier Part Number 1=541-2.00MLCT-ND, TempCo="100 ppm/C", Tolerance_%=1%, Value2=0.063W, Value_Code=2M00, ValueDisplayed=2.00M
R351: "RES, 100 k, 1%, 0.1 W, 0402", Manufacturer=Panasonic, Power_W=0.1, TempCo="100 ppm/C", Tolerance_%=1, Value1=1%, Value2=0.1W, Value_Code=100k
U2: "SINGLE SCHMITT-TRIGGER INVERTER GATE, DBV0005A", Alternate Manufacturer="Texas Instruments"
U5: "SimpleLink Sub-1 GHz Ultra-Low Power Wireless Microcontroller, RGZ0048A (VQFN-48)", Alternate Manufacturer="Texas Instruments", Alternate PartNumber=CC1310F128RGZT, Operating Temperature Range="-40 to 85 C", PartNumber=CC1310F128RGZR, Rating=Catalog
Y1: "Crystal, 32.768 KHz, 12.5 pF, SMD", Frequency="32.768 KHz", Frequency Stability=±20ppm, Manufacturer=Epson, Supplier Part Number 1=SE2413CT-ND
Y2: "Crystal, 24 MHz, 9 pF, SMD", Frequency Stability=+/-20ppm, Frequency_Fixed=24MHz, Manufacturer=Epson, PartNumber="TSX-3225 24.0000MF20G-AC3", Supplier Part Number 1=SER3634CT-ND
ZZ2 ZZ3 ZZ4: library part AssemblyNote, Alternate Manufacturer=-

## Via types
v1: diameter 0.711, hole 0.305, Top Layer to Bottom Layer, 239 vias
v2: diameter 0.5, hole 0.2, Top Layer to Bottom Layer, 21 vias
v3: diameter 1, hole 0.38, Top Layer to Bottom Layer, 19 vias
v4: diameter 0.61, hole 0.203, Top Layer to Bottom Layer, tented both sides, 8 vias
v5: diameter 3.175, hole 3.175, Top Layer to Bottom Layer, 2 vias
v6: diameter 0.864, hole 0.406, Top Layer to Bottom Layer, 1 vias
v7: diameter 1.27, hole 0.711, Top Layer to Bottom Layer, 1 vias
v8: diameter 1.9, hole 1.5, Top Layer to Bottom Layer, 1 vias

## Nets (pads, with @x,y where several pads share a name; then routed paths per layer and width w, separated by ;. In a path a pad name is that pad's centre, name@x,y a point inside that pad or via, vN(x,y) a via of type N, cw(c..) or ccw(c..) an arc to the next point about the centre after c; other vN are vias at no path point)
BASE_PWM: R28.1 R31.2 R33.2 R35.2 R37.2 U2.2 U5.39 | length 67
  Top Layer w0.203: v1(1.753,44.704) 3.327,44.704 3.912,45.288 R37.2@3.912,47.244 4.419,47.244 4.49,47.173 5.035,47.173 5.106,47.244 R35.2@5.613,47.244 5.639,47.219 R33.2@7.518,47.219 7.534,47.235 R31.2@9.296,47.235 9.923,47.235 ccw(c9.923,47.438) 10.045,47.275 ccw(c9.923,47.438) 10.067,47.294 10.644,47.871 cw(c10.787,47.727) 10.665,47.89 cw(c10.787,47.727) 10.787,47.93 11.989,47.93 12.497,48.438 U2.2@12.497,49.049 12.497,49.987 13.056,50.546 14.503,50.546 17.221,53.264 R28.1@17.221,59.309 ; v1(4.75,17.577) 5.272,17.577 5.827,17.021 10.163,17.021 11.187,18.045 11.187,20.865 11.988,21.665 11.988,22.124 U5.39@11.995,22.131
  Bottom Layer w0.203: v1(1.753,44.704) 2.17,44.287 2.17,28.775 ccw(c2.373,28.775) 2.211,28.653 ccw(c2.373,28.775) 2.229,28.632 2.76,28.101 cw(c2.616,27.957) 2.779,28.079 cw(c2.616,27.957) 2.819,27.957 2.819,19.507 v1(4.75,17.577)
BASE_PWM_N: J11.1 R29.2 U2.4 U5.40 | length 57.1
  Top Layer w0.203: J11.1@5.486,15.519 5.486,16.059 5.986,16.559 cw(c6.129,16.415) 6.129,16.618 10.739,16.618 11.633,17.512 11.633,20.312 cw(c11.836,20.312) 11.652,20.398 v4@11.711,20.523 ; v4(10.768,46.001) 11.448,46.001 U2.4@11.547,46.099 11.547,45.355 12.049,44.852 12.501,44.852 v1(12.598,44.755) ; v4@11.655,20.566 11.691,20.578 cw(c11.89,20.619) 11.743,20.759 12.182,21.225 cw(c12.329,21.084) 12.185,21.227 12.436,21.478 ccw(c12.292,21.622) 12.495,21.622 U5.40@12.495,22.131 ; v1(12.416,59.263) 12.416,58.441 R29.2@12.7,58.242
  Bottom Layer w0.203: v4(10.768,46.001) 11.542,46.775 11.901,46.775 13.691,48.564 13.691,57.689 ccw(c13.487,57.689) 13.642,57.821 v1(12.416,59.263) ; 11.055,21.353 v4(11.794,20.614) ; 11.053,21.354 cw(c11.198,21.496) 10.995,21.496 10.995,22.144 ccw(c10.792,22.144) 10.917,22.304 10.466,22.658 10.465,22.659 10.366,22.758 10.366,41.428 10.401,41.462 cw(c10.564,41.34) 10.419,41.483 12.598,43.663 v1(12.598,44.755)
BAT_IN: BT1.1 J1.1 | length 6.1
  Top Layer w0.762: J1.1@27.153,42.926 29.82,42.926 30.302,43.409 30.546,43.652 v7(31.116,43.652)
  Bottom Layer w0.762: BT1.1@28.096,40.081 28.945,40.081 BT1.1@29.008,40.018 28.159,40.018 BT1.1@28.096,40.081
CAP_EL: R24.1 | length 7.3
  Top Layer w0.254: v1(10.084,11.76) 10.084,10.457 10.336,10.205 ; v1(10.084,13.31) 10.208,13.31 10.303,13.215 12.032,13.215 12.33,13.513 R24.1@13.894,13.513 ; 10.922,6.121 11.049,6.121
  Bottom Layer w0.254: v1(10.084,11.76) v1(10.084,13.31)
COM1_1: LCD1.25 R30.1 R30.2 R31.1 U5.32 | length 70.8
  Top Layer w0.203: v1(5.588,25.4) 5.867,25.121 8.28,25.121 8.62,24.781 U5.32@10.345,24.781 ; R30.1@9.296,49.038 R30.2@9.296,50.054 9.296,50.419 v1@9.538,50.66 ; v1(9.474,50.698) 9.502,50.727 9.502,51.278 9.754,51.529 9.754,71.772 cw(c9.957,71.772) 9.794,71.894 cw(c9.957,71.772) 9.812,71.915 11.176,73.279 11.176,85.921 LCD1.25@11.201,85.946
  Top Layer w0.254: R31.1@9.296,48.251 R30.1@9.296,49.038
  Bottom Layer w0.203: v1(5.588,25.4) 5.636,25.448 5.636,33.884 ccw(c5.432,33.884) 5.576,34.027 5.105,34.498 5.105,44.425 9.415,48.734 ccw(c9.271,48.878) 9.434,48.756 ccw(c9.271,48.878) 9.474,48.878 v1(9.474,50.698)
COM2_1: LCD1.26 R32.1 R32.2 R33.1 U5.36 | length 87.7
  Top Layer w0.203: v1(6.096,19.431) 6.096,19.507 7.239,18.364 9.601,18.364 9.928,18.691 9.928,21.587 10.345,22.004 U5.36@10.345,22.781 ; R33.1@7.518,48.235 8.052,48.235 8.255,48.438 8.255,51.156 7.722,51.689 6.096,51.689 4.572,53.213 4.572,59.334 7.315,62.078 7.315,70.815 8.661,72.161 LCD1.26@8.661,85.946 ; R32.1@7.518,49.038 R32.2@7.518,50.054 7.518,50.749 7.544,50.724 v1(7.569,50.724)
  Top Layer w0.254: R33.1@7.518,48.235 R32.1@7.518,49.038
  Bottom Layer w0.203: v1(6.096,19.431) 4.169,21.358 4.169,27.74 4.826,28.397 4.826,33.985 4.445,34.366 4.445,44.602 7.569,47.727 v1(7.569,50.724)
COM3_1: LCD1.27 R34.1 R34.2 R35.1 U5.37 | length 82.1
  Top Layer w0.203: R34.1@5.686,49.047 5.918,49.047 6.502,49.632 6.502,50.292 3.962,52.832 3.962,60.401 4.699,61.138 4.699,76.606 6.096,78.003 6.096,85.921 LCD1.27@6.121,85.946 ; v1(5.969,18.415) 6.502,17.882 9.855,17.882 10.331,18.358 10.331,21.287 10.995,21.951 U5.37@10.995,22.131
  Top Layer w0.254: v1(4.763,47.83) 5.119,48.186 cw(c5.298,48.006) 5.298,48.26 R35.1@5.613,48.26 ; R35.1@5.613,48.285 R34.1@5.613,48.997 ; R34.1@5.613,49.047 R34.2@5.613,50.063
  Bottom Layer w0.203: v1(4.763,47.83) 3.229,46.297 3.229,30.582 3.658,30.153 3.658,20.726 v1(5.969,18.415)
COM4_1: LCD1.28 R36.1 R36.2 R37.1 U5.38 | length 82.6
  Top Layer w0.203: v1(2.21,45.644) 2.21,46.609 R36.2@2.337,46.736 R36.1@2.337,47.752 ; 2.972,48.26 2.464,47.752 R36.1@2.337,47.752 ; LCD1.28@3.581,85.946 3.581,80.467 1.346,78.232 1.346,48.909 2.337,47.919 R36.1@2.337,47.752 ; v1(4.877,18.542) 5.994,17.424 9.957,17.424 10.011,17.478 10.022,17.478 10.734,18.191 10.734,20.982 11.488,21.736 11.488,22.124 U5.38@11.495,22.131
  Top Layer w0.254: 2.972,48.26 R37.1@3.912,48.26
  Bottom Layer w0.203: v1(2.21,45.644) 2.743,45.11 2.743,29.574 ccw(c2.946,29.574) 2.784,29.452 ccw(c2.946,29.574) 2.802,29.43 3.167,29.066 cw(c3.023,28.923) 3.185,29.045 cw(c3.023,28.923) 3.226,28.923 3.226,20.193 v1(4.877,18.542)
DCDC_SW: L331.1 U5.33 | length 3
  Top Layer w0.2: L331.1@7.468,24.003 7.746,24.281 U5.33@10.345,24.281
DIO_1: LCD1.15 R22.2 U5.6 | length 80.2
  Top Layer w0.203: U5.6@17.145,25.281 18.3,25.281 20.904,27.886 20.904,29.808 22.109,31.013 24.895,33.799 cw(c25.038,33.655) 24.916,33.818 cw(c25.038,33.655) 25.038,33.858 39.04,33.858 39.285,34.103 ccw(c39.141,34.247) 39.345,34.247 39.354,43.126 ccw(c38.227,43.129) 39.354,43.129 39.354,56.984 ccw(c39.052,56.984) 39.354,56.987 39.347,57.887 39.03,58.203 R22.2@39.03,59.411 38.924,59.517 38.924,60.669 39.294,61.039 39.294,65.557
  Top Layer w0.254: LCD1.15@36.601,85.946 36.576,85.921 36.576,77.47 37.503,76.543 37.503,67.348 39.294,65.557
DIO_2: J2.2 R25.2 U5.7 | length 57.7
  Top Layer w0.203: U5.7@17.145,25.781 18.02,25.781 20.371,28.132 20.371,29.845 25.857,35.331 v1(34.493,35.331) ; v1(37.284,63.154) 37.422,63.154 37.618,62.957 R25.2@38.456,62.957
  Bottom Layer w0.203: v1(34.493,35.331) 35.636,36.474 38.71,36.474 39.446,37.211 39.446,52.4 J2.2@38.227,53.619 36.601,55.245 36.601,56.794 38.481,58.674 38.481,61.873 ccw(c38.278,61.873) 38.44,61.995 ccw(c38.278,61.873) 38.422,62.016 v1(37.284,63.154)
DIO_3: J3.2 U5.8 | length 26.4
  Top Layer w0.203: U5.8@17.145,26.281 17.95,26.281 19.914,28.245 19.914,30.048 26.187,36.322 34.229,36.322 35.626,37.719 J3.2@37.77,37.719
DIO_4: LCD1.13 R27.2 U5.9 | length 49.8
  Top Layer w0.203: U5.9@17.145,26.781 17.815,26.781 19.482,28.448 19.482,30.226 28.499,39.243 30.95,39.243 34.379,42.672 34.379,57.036 35.956,58.612 ; LCD1.13@34.061,65.946 34.061,65.405 34.544,64.922 34.544,62.643 ccw(c34.747,62.644) 34.603,62.502 35.295,61.81 cw(c35.151,61.666) 35.313,61.788 cw(c35.151,61.666) 35.354,61.666 35.354,61.479 ccw(c35.557,61.479) 35.413,61.336 ; 35.414,61.335 R27.2@36.322,60.427 ; 35.956,58.613 ccw(c35.811,58.755) 35.974,58.634 ccw(c35.811,58.755) 36.014,58.755 36.014,60.127 cw(c36.218,60.127) 36.019,60.17 36.032,60.228 R27.2@36.23,60.427
DIO_5: LCD1.12 R4.1 U5.10 | length 49.4
  Top Layer w0.203: U5.10@17.145,27.281 17.745,27.281 18.974,28.51 18.974,30.391 28.461,39.878 30.658,39.878 33.647,42.867 ccw(c33.503,43.01) 33.665,42.888 ccw(c33.503,43.01) 33.706,43.01 33.706,57.371 cw(c33.909,57.371) 33.746,57.493 cw(c33.909,57.371) 33.764,57.513 34.888,58.637 ccw(c34.744,58.78) 34.947,58.78 34.947,61.006 ccw(c34.744,61.006) 34.888,61.15 34.781,61.256 ccw(c34.638,61.112) 34.638,61.316 34.214,61.316 34.214,61.646 31.496,64.364 31.496,65.921 LCD1.12@31.521,65.946
DIO_6: LCD1.11 R7.1 U5.11 | length 48.5
  Top Layer w0.203: U5.11@17.145,27.781 17.675,27.781 18.44,28.547 18.44,30.428 28.441,40.429 cw(c28.584,40.284) 28.462,40.447 cw(c28.584,40.284) 28.584,40.488 30.345,40.488 ccw(c30.345,40.691) 30.467,40.528 ccw(c30.345,40.691) 30.488,40.546 33.136,43.194 33.136,55.307 32.433,56.01 32.433,56.025 32.048,56.41 32.033,56.41 31.016,57.427 cw(c31.16,57.57) 30.957,57.57 30.956,60.881 30.956,61.366 cw(c31.159,61.366) 31.159,61.57 R7.1@31.658,61.57 ; LCD1.11@28.981,65.946 28.981,64.922 31.351,62.553 cw(c31.187,62.388) 31.42,62.388 R7.1@31.42,61.808
DIO_7: LCD1.7 R13.1 U5.12 | length 46.4
  Top Layer w0.203: v1(16.29,47.439) 16.719,47.439 22.123,52.843 22.123,58.217 21.006,59.334 21.869,60.198 21.869,61.493 18.796,64.567 18.796,65.921 LCD1.7@18.821,65.946 ; U5.12@17.147,28.281 U5.12@17.145,28.281 17.958,29.094 17.958,34.442 16.398,36.002 16.398,42.433 18.758,44.793 19.291,44.793 v1(19.304,44.78)
  Bottom Layer w0.203: v1(16.29,47.439) 16.646,47.439 v1(19.304,44.78)
DIO_8: LCD1.10 R2.1 U5.14 | length 44.9
  Top Layer w0.203: U5.14@15.995,28.931 15.995,42.868 30.494,57.367 ccw(c30.35,57.51) 30.512,57.388 ccw(c30.35,57.51) 30.553,57.51 30.553,61.903 30.124,62.332 29.794,62.332 29.794,62.509 ccw(c29.591,62.509) 29.735,62.653 29.204,63.183 ccw(c29.06,63.04) 29.203,63.184 ; LCD1.10@26.441,65.946 29.202,63.185
DIO_10: LCD1.9 R1.1 U5.16 | length 46
  Top Layer w0.203: U5.16@14.995,28.931 14.995,43.341 28.132,56.478 ccw(c27.988,56.621) 28.15,56.499 ccw(c27.988,56.621) 28.191,56.621 28.191,58.62 28.737,59.166 R1.1@28.737,60.325 ; LCD1.9@23.901,65.946 23.876,65.921 23.876,64.448 ccw(c24.079,64.448) 23.917,64.326 ccw(c24.079,64.448) 23.935,64.304 25.087,63.153 ccw(c25.23,63.297) 25.108,63.134 ccw(c25.23,63.297) 25.23,63.094 27.018,63.094 cw(c27.018,62.89) 27.14,63.053 cw(c27.018,62.89) 27.161,63.034 28.663,61.532 cw(c28.52,61.389) 28.723,61.389 28.723,60.387 R1.1@28.534,60.198
DIO_11: LCD1.21 R16.2 U5.17 | length 66.7
  Top Layer w0.203: U5.17@14.495,28.931 14.495,43.451 25.933,54.889 R16.2@25.933,56.118 25.933,56.218 26.132,56.417 26.622,56.417 27.788,57.582 27.788,61.689 ccw(c27.584,61.689) 27.728,61.832 27.364,62.196 ccw(c27.221,62.052) 27.343,62.215 ccw(c27.221,62.052) 27.221,62.255 25.222,62.255 22.682,64.795 22.682,75.463 21.361,76.784 LCD1.21@21.361,85.946
DIO_12: LCD1.8 R14.1 U5.18 | length 48.6
  Top Layer w0.203: U5.18@13.995,28.931 13.995,43.586 16.7,46.291 16.711,46.291 23.111,52.69 23.111,52.702 23.333,52.924 ccw(c23.19,53.068) 23.393,53.069 v4(23.368,58.29) ; LCD1.8@21.361,65.946 21.361,64.821 24.74,61.443 R14.1@25.603,61.443
  Bottom Layer w0.203: LCD1.8@21.361,65.946 21.235,65.82 21.235,62.127 23.368,59.995 v4(23.368,58.29)
DIO_13: LCD1.22 R15.2 U5.19 | length 65.1
  Top Layer w0.203: U5.19@13.495,28.931 13.495,43.645 13.592,43.742 13.592,43.753 16.533,46.694 16.544,46.694 22.708,52.857 22.708,58.793 cw(c22.911,58.793) 22.748,58.915 cw(c22.911,58.793) 22.767,58.936 24.409,60.579 ; LCD1.22@18.821,85.946 18.844,85.924 18.844,75.898 20.193,74.549 20.193,64.795 24.409,60.579 ; R15.2@25.603,60.401 24.587,60.401 24.409,60.579
DIO_14: LCD1.3 R3.1 U5.20 | length 44.8
  Top Layer w0.203: LCD1.3@8.661,65.946 8.636,65.921 8.636,59.08 8.992,58.725 8.992,55.27 v1@8.763,55.042 ; v1(9.601,44.831) 12.995,41.437 U5.20@12.995,28.931 ; v1(11.786,54.508) 11.76,54.508 11.811,54.458 R3.1@12.497,54.458
  Bottom Layer w0.203: v1(8.814,55.042) 9.347,54.508 12.144,54.508 cw(c12.144,54.305) 12.287,54.449 13.022,53.714 cw(c12.878,53.571) 13.04,53.693 cw(c12.878,53.571) 13.081,53.571 13.081,48.525 11.953,47.396 11.184,47.396 ccw(c11.184,47.193) 11.062,47.356 ccw(c11.184,47.193) 11.041,47.337 9.813,46.109 ccw(c9.957,45.966) 9.794,46.088 ccw(c9.957,45.966) 9.754,45.966 9.754,45.068 cw(c9.55,45.068) 9.694,44.924 v1(9.601,44.831)
DIO_15: LCD1.2 R20.2 U5.21 | length 51.8
  Top Layer w0.203: v1@7.036,38.71 8.103,37.643 8.103,36.216 8.218,36.1 ccw(c8.362,36.244) 8.362,36.041 9.417,36.041 cw(c9.417,35.837) 9.561,35.981 12.495,33.047 U5.21@12.495,28.931 ; v1(11.913,53.492) 12.725,53.492 13.691,54.458 14.995,55.762 ; 14.996,55.763 ccw(c14.851,55.906) 15.014,55.784 ccw(c14.851,55.906) 15.054,55.906 v1(15.054,58.412)
  Bottom Layer w0.203: LCD1.2@6.121,65.946 6.147,65.921 6.147,62.814 6.172,62.789 6.172,62.763 13.519,62.763 14.012,62.271 cw(c13.868,62.127) 14.072,62.127 14.072,59.479 ccw(c14.275,59.479) 14.13,59.336 ; v1(6.985,38.71) 7.358,39.082 7.358,44.585 11.541,48.768 11.541,48.808 11.709,48.977 11.709,52.207 11.913,52.411 v1(11.913,53.492) ; 14.131,59.335 v1(15.054,58.412)
DIO_18: LCD1.6 R10.1 U5.28 | length 54.5
  Top Layer w0.203: v1(8.56,27.61) 8.56,27.762 9.541,26.781 U5.28@10.345,26.781 ; LCD1.6@16.281,65.946 16.256,65.921 16.256,64.16 17.472,62.944 19.101,62.944 20.98,61.065 R10.1@20.98,60.604
  Bottom Layer w0.203: v1(8.56,27.61) 7.569,28.6 7.569,35.298 cw(c7.772,35.298) 7.61,35.42 cw(c7.772,35.298) 7.628,35.441 9.034,36.847 ccw(c8.89,36.99) 9.053,36.868 ccw(c8.89,36.99) 9.093,36.99 9.093,42.24 15.57,48.717 15.57,52.273 14.931,52.912 14.931,54.864 15.799,55.732 15.799,58.597 14.554,59.842 14.554,62.408 16.281,64.135 LCD1.6@16.281,65.946
DIO_19: LCD1.24 R26.2 U5.29 | length 71.3
  Top Layer w0.203: v1(7.696,27.153) 8.153,26.695 9.017,26.695 9.431,26.281 U5.29@10.345,26.281 ; v1(14.91,49.835) 14.91,49.987 17.932,53.01 17.932,53.221 v1@18.051,53.34
  Top Layer w0.254: LCD1.24@13.716,85.921 13.716,77.114 15.113,75.717 15.113,63.605 ccw(c15.367,63.605) 15.164,63.453 ccw(c15.367,63.605) 15.187,63.426 v4(16.535,62.078) 16.715,61.898 ccw(c16.895,62.078) 16.895,61.824 R26.2@17.196,61.824
  Bottom Layer w0.203: v1(7.696,27.153) 7.112,27.737 7.112,35.527 cw(c7.315,35.527) 7.153,35.649 cw(c7.315,35.527) 7.171,35.67 8.45,36.949 ccw(c8.306,37.092) 8.468,36.97 ccw(c8.306,37.092) 8.509,37.092 8.509,42.226 14.783,48.5 14.783,49.708 v1(14.91,49.835)
  Bottom Layer w0.254: v4(16.535,62.078) 18.299,62.078 19.723,60.653 cw(c19.544,60.474) 19.798,60.474 19.798,57.952 cw(c19.544,57.952) 19.747,57.8 cw(c19.544,57.952) 19.723,57.773 17.958,56.007 v1(17.958,53.569)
